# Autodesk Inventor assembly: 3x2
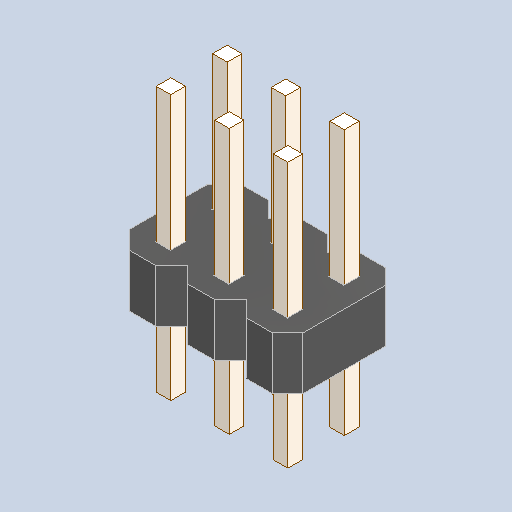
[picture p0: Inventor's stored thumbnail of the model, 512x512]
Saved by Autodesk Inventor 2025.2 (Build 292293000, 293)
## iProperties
Created: 2025-04
Part Number: 3x2
Description: PART--DESC
Document SubType Name: Assembly
Designer: BennF
Author: BennF
Revision Number: NONE
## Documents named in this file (3)
- C:\Users\BennF\Nextcloud\Benutzer\CNC JarBeRi\existing parts\Electronics\RepRap A4988 Shied (USE WITHOUT ARDUINO)\reprap-a4988-1.snapshot.1\RepRap\RepRap\3x2_1.iam
- C:\Users\BennF\Nextcloud\Benutzer\CNC JarBeRi\existing parts\Electronics\RepRap A4988 Shied (USE WITHOUT ARDUINO)\reprap-a4988-1.snapshot.1\RepRap\RepRap\3x2 Geometry.ipt
- C:\Users\BennF\Nextcloud\Benutzer\CNC JarBeRi\existing parts\Electronics\RepRap A4988 Shied (USE WITHOUT ARDUINO)\reprap-a4988-1.snapshot.1\RepRap\RepRap\pin10.ipt
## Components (2 placed, 2 different names)
1. 3x2 Geometry
2. pin10
